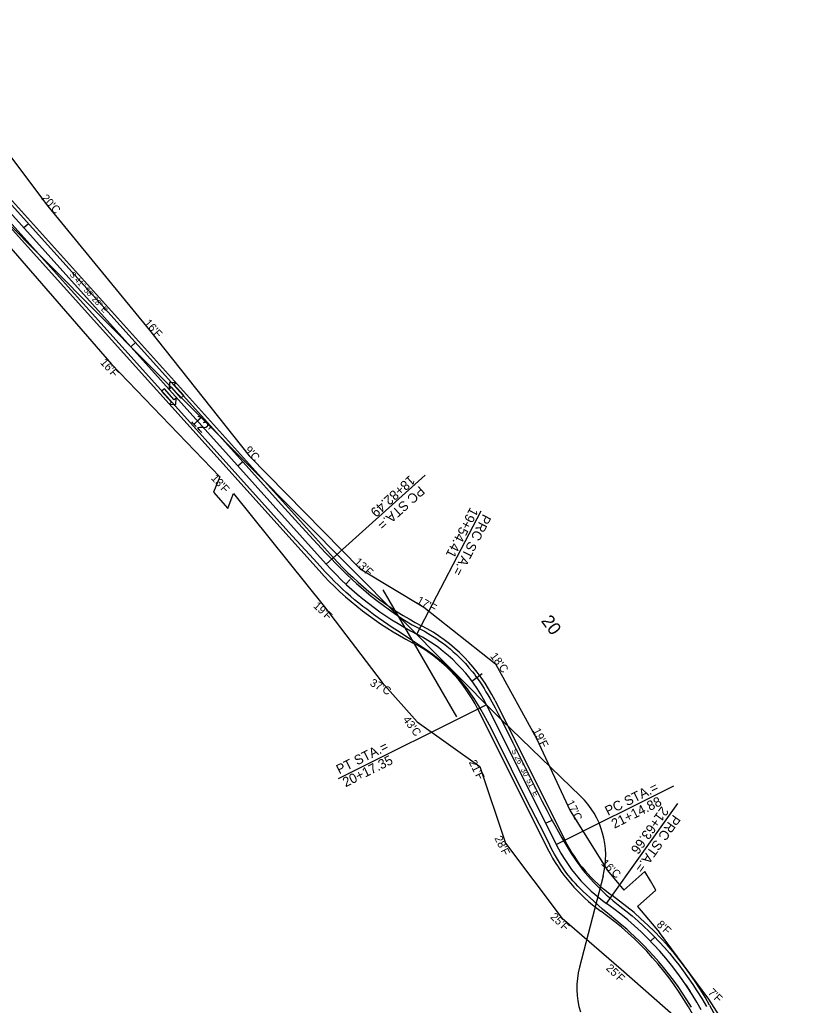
# Model space of a CAD drawing. Extents: x 1968740 to 1970715, y 796044 to 797557.
# Drawn here: x 1969951 to 1970448, y 796745 to 797361 of the extents above; entities that cross this region are included whole.
import ezdxf

# ---------------------------------------------------------------- set-up
doc = ezdxf.new("R2010")
doc.units = 0
for name, color, linetype in [('RD_HC_CL_Rel', 7, 'Continuous'), ('RD_HC_Data_Rel', 7, 'Continuous'), ('RD_PD_ALT3_CL', 7, 'Continuous'), ('RD_PD_ALT4_CL', 7, 'Continuous'), ('RD_PD_ALT5_CL', 7, 'Continuous'), ('RD_PD_CstnLmt', 7, 'Continuous'), ('RD_PD_CstnLmt_TX', 7, 'Continuous'), ('RD_PD_Final_TrvlWay', 7, 'Continuous'), ('RD_SHT_TX', 7, 'Continuous')]:
    doc.layers.add(name, color=color, linetype=linetype)

msp = doc.modelspace()

# ---------------------------------------------------------------- linework, layer by layer
at = {"layer": 'RD_HC_CL_Rel'}
for p, q in [((1969840.13, 797356.88), (1970142.43, 797020.84)), ((1970242.44, 796932.95), (1970285.98, 796845.68))]:
    msp.add_line(p, q, dxfattribs=at)
for centre, radius, start, end in [((1970291.12, 797154.6), 200, 221.97435, 242.57811), ((1970152.96, 796888.31), 100, 26.5143, 62.57811), ((1970375.46, 796890.32), 100, 206.5143, 234.46356), ((1970201.1, 796646.2), 200, 28.75441, 54.46356)]:
    msp.add_arc(centre, radius, start, end, dxfattribs=at)
at = {"layer": 'RD_HC_Data_Rel'}
for p, q in [((1969953.51, 797230.85), (1969956.48, 797233.53)), ((1970020.39, 797156.51), (1970023.36, 797159.19)), ((1970087.26, 797082.17), (1970090.24, 797084.84)), ((1970142.43, 797020.84), (1970204.22, 797076.42)), ((1970199.01, 796977.07), (1970239.03, 797054.19)), ((1970154.7, 797008.35), (1970157.43, 797011.28)), ((1970233.39, 796947.73), (1970239.83, 796952.48)), ((1970242.44, 796932.95), (1970149.95, 796886.81)), ((1970285.98, 796845.68), (1970359.4, 796882.31)), ((1970317.34, 796808.95), (1970361.96, 796871.42)), ((1970279.34, 796859), (1970282.92, 796860.78)), ((1970344.84, 796785.26), (1970347.71, 796788.05)), ((1970366.85, 796758.11), (1970369.6, 796753.94))]:
    msp.add_line(p, q, dxfattribs=at)
at = {"layer": 'RD_PD_ALT3_CL'}
for p, q in [((1969840.13, 797356.88), (1970142.43, 797020.84)), ((1970177.69, 797004.8), (1970223.77, 796925.44)), ((1970242.44, 796932.95), (1970285.98, 796845.68))]:
    msp.add_line(p, q, dxfattribs=at)
for centre, radius, start, end in [((1970291.12, 797154.6), 200, 221.97435, 242.57811), ((1970152.96, 796888.31), 100, 26.5143, 62.57811), ((1970375.46, 796890.32), 100, 206.5143, 234.46356), ((1970201.1, 796646.2), 200, 28.75441, 54.46356)]:
    msp.add_arc(centre, radius, start, end, dxfattribs=at)
at = {"layer": 'RD_PD_ALT4_CL'}
for p, q in [((1970251.76, 796923.56), (1969830.46, 797348.01)), ((1970301.11, 796875.95), (1970251.76, 796923.56)), ((1970315.22, 796825.99), (1970300.48, 796769.02))]:
    msp.add_line(p, q, dxfattribs=at)
for centre, start, end in [((1970265.36, 796838.89), 345.49821, 46.02957), ((1970350.34, 796756.12), 165.49821, 196.92504)]:
    msp.add_arc(centre, 51.5, start, end, dxfattribs=at)
at = {"layer": 'RD_PD_ALT5_CL'}
for p, q in [((1969840.13, 797356.88), (1970142.43, 797020.84)), ((1970242.44, 796932.95), (1970285.98, 796845.68))]:
    msp.add_line(p, q, dxfattribs=at)
for points in [[(1970370.39, 796744.21), (1970367.57, 796748.68), (1970364.84, 796752.83), (1970362.02, 796756.93), (1970359.1, 796760.98), (1970356.09, 796764.95), (1970352.99, 796768.85), (1970350.01, 796772.43), (1970346.73, 796776.18), (1970343.58, 796779.61), (1970340.59, 796782.73), (1970337.77, 796785.55), (1970335.13, 796788.08), (1970332.19, 796790.78), (1970329.95, 796792.77), (1970327.17, 796795.16), (1970319.22, 796801.76), (1970314.92, 796805.41), (1970309.71, 796810.03), (1970306.79, 796812.73), (1970304.77, 796814.49), (1970302.82, 796816.31), (1970301.15, 796817.94), (1970299.53, 796819.61), (1970297.96, 796821.32), (1970296.42, 796823.06), (1970294.93, 796824.84), (1970293.48, 796826.65), (1970292.07, 796828.5), (1970290.7, 796830.37), (1970288.64, 796833.39), (1970286.69, 796836.47), (1970284.84, 796839.63), (1970283.26, 796842.57), (1970281.91, 796845.27), (1970278.01, 796853.45), (1970273.26, 796862.59), (1970267.09, 796874.74), (1970257.99, 796892.87), (1970245.51, 796917.87), (1970243.07, 796922.6), (1970240.85, 796926.69), (1970238.88, 796930.15), (1970236.83, 796933.56), (1970234.69, 796936.91), (1970232.63, 796939.92), (1970230.49, 796942.87), (1970228.26, 796945.75), (1970225.93, 796948.55), (1970223.51, 796951.28), (1970221.69, 796953.21), (1970220.05, 796954.85), (1970218.38, 796956.46), (1970216.67, 796958.03), (1970214.92, 796959.56), (1970213.13, 796961.05), (1970211.04, 796962.7), (1970208.92, 796964.31), (1970205.42, 796966.83), (1970201.03, 796969.84), (1970198, 796971.86), (1970186.9, 796979.09), (1970183.6, 796981.29), (1970178.12, 796985.01), (1970174.86, 796987.3), (1970171.9, 796989.45), (1970167.66, 796992.64), (1970165.29, 796994.47), (1970162.69, 796996.54), (1970160.12, 796998.65), (1970157.59, 797000.81), (1970154.85, 797003.23), (1970152.4, 797005.47), (1970149.98, 797007.75), (1970147.6, 797010.07), (1970145.03, 797012.67), (1970141.83, 797016.05), (1970138.7, 797019.5), (1970134.39, 797024.12), (1970129.43, 797029.5), (1970121.15, 797038.6), (1970109.56, 797051.43), (1969847.75, 797342.43)], [(1969863.24, 797337.18), (1970079.53, 797096.75), (1970112.39, 797060.25), (1970125.17, 797046.14), (1970134.42, 797036.03), (1970141.94, 797027.98), (1970145.4, 797024.35), (1970148.42, 797021.23), (1970151.94, 797017.67), (1970155.28, 797014.4), (1970158.43, 797011.41), (1970161.38, 797008.7), (1970164.38, 797006.05), (1970167.44, 797003.45), (1970170.54, 797000.92), (1970173.95, 796998.23), (1970177.94, 796995.22), (1970181.98, 796992.28), (1970186.34, 796989.22), (1970191.3, 796985.87), (1970196.1, 796982.84), (1970199.79, 796980.99), (1970201.62, 796980.05), (1970203.72, 796978.9), (1970206.06, 796977.55), (1970207.79, 796976.5), (1970209.77, 796975.23), (1970211.45, 796974.11), (1970213.37, 796972.77), (1970215.52, 796971.19), (1970217.62, 796969.56), (1970219.69, 796967.87), (1970221.7, 796966.13), (1970223.68, 796964.34), (1970225.6, 796962.49), (1970227.48, 796960.6), (1970229.08, 796958.91), (1970230.42, 796957.43), (1970231.51, 796956.17), (1970233.64, 796953.6), (1970234.88, 796952.03), (1970235.88, 796950.7), (1970237.83, 796947.99), (1970239.5, 796945.48), (1970240.92, 796943.21), (1970242.11, 796941.18), (1970243.24, 796939.12), (1970244.44, 796937.12), (1970245.78, 796934.8), (1970247.86, 796930.99), (1970250.04, 796926.85), (1970251.42, 796924.17), (1970253.81, 796919.38), (1970258.81, 796909.14), (1970269.44, 796887.95), (1970277, 796873.07), (1970280.06, 796867.14), (1970282.7, 796862.13), (1970285.07, 796857.72), (1970287.31, 796853.63), (1970289.45, 796849.86), (1970291.46, 796846.4), (1970293.36, 796843.26), (1970295.32, 796840.15), (1970297.15, 796837.36), (1970298.86, 796834.89), (1970300.62, 796832.46), (1970302.23, 796830.33), (1970303.89, 796828.25), (1970305.6, 796826.21), (1970307.36, 796824.21), (1970309.39, 796822.01), (1970311.46, 796819.85), (1970313.59, 796817.74), (1970315.27, 796816.13), (1970317.21, 796814.32), (1970319.19, 796812.54), (1970321.43, 796810.56), (1970325.75, 796807.28), (1970329.44, 796804.35), (1970333.31, 796801.14), (1970337.08, 796797.84), (1970340.52, 796794.68), (1970343.89, 796791.45), (1970346.95, 796788.37), (1970350.17, 796784.99), (1970353.53, 796781.29), (1970356.59, 796777.75), (1970359.56, 796774.15), (1970362.45, 796770.48), (1970365.26, 796766.74), (1970367.78, 796763.21), (1970371.17, 796758.24), (1970373.74, 796754.32), (1970376.77, 796749.48), (1970379.69, 796744.58)]]:
    msp.add_lwpolyline(points, dxfattribs=at)
for centre in [(1970142.43, 797020.84), (1970142.43, 797020.84), (1970199.01, 796977.07), (1970199.01, 796977.07), (1970242.44, 796932.95), (1970242.44, 796932.95), (1970285.98, 796845.68), (1970285.98, 796845.68), (1970317.34, 796808.95), (1970317.34, 796808.95)]:
    msp.add_circle(centre, 0.0417, dxfattribs=at)
for centre, radius, start, end in [((1970291.12, 797154.6), 200, 221.97435, 242.57811), ((1970152.96, 796888.31), 100, 26.5143, 62.57811), ((1970375.46, 796890.32), 100, 206.5143, 234.46356), ((1970201.1, 796646.2), 200, 28.75441, 54.46356)]:
    msp.add_arc(centre, radius, start, end, dxfattribs=at)
at = {"layer": 'RD_PD_CstnLmt'}
for p, q in [((1969908.25, 797324.65), (1969968.59, 797244.43)), ((1969968.59, 797244.43), (1970032.11, 797167.06)), ((1969942.82, 797221.25), (1970008.45, 797145.77)), ((1970032.11, 797167.06), (1970094.25, 797088.45)), ((1970008.45, 797145.77), (1970075.91, 797075.33)), ((1970094.25, 797088.45), (1970163.6, 797017.9)), ((1970075.91, 797075.33), (1970071.96, 797065.73)), ((1970071.96, 797065.73), (1970080.99, 797055.61)), ((1970080.99, 797055.61), (1970083.05, 797061.16)), ((1970083.05, 797061.16), (1970084.58, 797064.88)), ((1970084.58, 797064.88), (1970141.43, 796994.13)), ((1970163.6, 797017.9), (1970203.28, 796994.06)), ((1970141.43, 796994.13), (1970177.43, 796946.81)), ((1970203.28, 796994.06), (1970248.01, 796958.53)), ((1970248.01, 796958.53), (1970273.64, 796912.03)), ((1970177.43, 796946.81), (1970199.08, 796922.38)), ((1970199.08, 796922.38), (1970238.26, 796894.38)), ((1970273.64, 796912.03), (1970294.71, 796866.66)), ((1970238.26, 796894.38), (1970254.4, 796846.55)), ((1970294.71, 796866.66), (1970317.94, 796829.42)), ((1970254.4, 796846.55), (1970289.73, 796799.55)), ((1970317.94, 796829.42), (1970328.2, 796817.2)), ((1970341.36, 796828.96), (1970328.2, 796817.2)), ((1970344.82, 796822.99), (1970341.36, 796828.96)), ((1970348.19, 796817.2), (1970344.82, 796822.99)), ((1970336.76, 796806.99), (1970348.19, 796817.2)), ((1970336.76, 796806.99), (1970350.44, 796790.69)), ((1970326.56, 796767.58), (1970289.73, 796799.55)), ((1970381.25, 796749.08), (1970350.44, 796790.69)), ((1970360.82, 796737.41), (1970326.56, 796767.58)), ((1970408.3, 796706.75), (1970381.25, 796749.08))]:
    msp.add_line(p, q, dxfattribs=at)
at = {"layer": 'RD_PD_Final_TrvlWay'}
for p, q in [((1969844.59, 797360.89), (1970146.89, 797024.85)), ((1969835.67, 797352.87), (1970137.97, 797016.83)), ((1970247.81, 796935.63), (1970291.35, 796848.36)), ((1970237.07, 796930.27), (1970280.61, 796843)), ((1970381.69, 796745.3), (1970447.67, 796625.07))]:
    msp.add_line(p, q, dxfattribs=at)
for centre, radius, start, end in [((1970291.12, 797154.6), 194, 221.97435, 242.57811), ((1970291.12, 797154.6), 206, 221.97435, 242.57811), ((1970152.96, 796888.31), 106, 26.5143, 62.57811), ((1970152.96, 796888.31), 94, 26.5143, 62.57811), ((1970375.46, 796890.32), 94, 206.5143, 234.46356), ((1970375.46, 796890.32), 106, 206.5143, 234.46356), ((1970201.1, 796646.2), 206, 28.75441, 54.46356), ((1970201.1, 796646.2), 194, 28.75441, 54.46356)]:
    msp.add_arc(centre, radius, start, end, dxfattribs=at)
at = {"layer": 'RD_SHT_TX'}
for points in [[(1970051.7, 797124.56), (1970053.49, 797126.16), (1970047.39, 797133.01), (1970048.61, 797134.09), (1970044.62, 797134.32), (1970044.39, 797130.33), (1970045.6, 797131.41)], [(1970041.46, 797130.37), (1970039.67, 797128.78), (1970045.77, 797121.93), (1970044.55, 797120.85), (1970048.54, 797120.61), (1970048.78, 797124.61), (1970047.56, 797123.52)]]:
    msp.add_lwpolyline(points, close=True, dxfattribs=at)

# ---------------------------------------------------------------- texts
at = {"layer": 'RD_HC_Data_Rel'}
for s, height, rotation, p in [('S 41%%d 58\' 28" E', 3.6, 311.97435, (1969982.05, 797201.52)), ('18+82.49', 6, 221.97435, (1970194.56, 797076.71)), ('PC STA.=', 6, 221.97435, (1970200.58, 797070.02)), ('19+54.41', 6, 242.57811, (1970232.34, 797056.71)), ('PRC STA.=', 6, 242.57811, (1970240.33, 797052.56)), ('20', 8, 306.45595, (1970276.21, 796985.35)), ('PT STA.=', 6, 26.5143, (1970150.49, 796889.46)), ('20+17.35', 6, 26.5143, (1970154.51, 796881.41)), ('S 26%%d 30\' 51" E', 3.6, 296.5143, (1970257.83, 796904.34)), ('PC STA.=', 6, 26.5143, (1970318.24, 796863.59)), ('21+14.88', 6, 26.5143, (1970322.26, 796855.53)), ('21+63.66', 6, 234.46356, (1970351.79, 796869.99)), ('PRC STA.=', 6, 234.46356, (1970359.11, 796864.76))]:
    msp.add_text(s, height=height, rotation=rotation, dxfattribs=at).set_placement(p)
at = {"layer": 'RD_PD_CstnLmt_TX'}
for s, rotation, p in [("20'C", 311.97435, (1969964.31, 797249.19)), ("16'F", 311.97435, (1970028.4, 797171.18)), ("16'F", 311.97435, (1970001.02, 797146.55)), ("9'C", 311.97435, (1970091.13, 797091.91)), ("13'F", 311.97435, (1970070.22, 797074.29)), ("13'F", 316.9913, (1970159.54, 797021.68)), ("17'F", 331.31524, (1970198.41, 796996.72)), ("19'F", 316.9913, (1970133.97, 796994.26)), ("18'C", 306.45592, (1970244.49, 796963.29)), ("37'C", 331.31524, (1970169.29, 796945.27)), ("43'C", 306.45592, (1970190.02, 796923.65)), ("19'F", 296.5143, (1970271.17, 796917)), ("21'F", 296.5143, (1970231.31, 796897.11)), ("17'C", 296.5143, (1970292.06, 796871.97)), ("28'F", 296.5143, (1970247.23, 796849.72)), ("16'C", 316.63814, (1970313.63, 796833.48)), ("25'F", 316.63814, (1970281.92, 796800.05)), ("8'F", 316.63814, (1970348.25, 796795.22)), ("25'F", 316.63814, (1970316.63, 796767.99)), ("7'F", 316.63814, (1970380.33, 796752.77))]:
    msp.add_text(s, height=5, rotation=rotation, dxfattribs=at).set_placement(p)
at = {"layer": 'RD_SHT_TX'}
msp.add_text("12'", height=7, rotation=313.66908, dxfattribs=at).set_placement((1970057.68, 797109.96))

doc.saveas('drawing.dxf')
